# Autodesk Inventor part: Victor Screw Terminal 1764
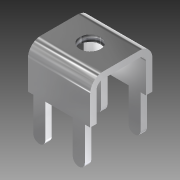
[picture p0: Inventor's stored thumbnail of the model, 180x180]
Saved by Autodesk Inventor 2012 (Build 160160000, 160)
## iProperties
Shininess: 86.0
Length Units: 11272
Angle Units: 11279
Time Units: 11290
Mass Units: 11286
Length Display Precision: 3
Angle Display Precision: 2
Created: 2005-12
Part Number: Victor Screw Terminal 1764
Material: Bronze, Soft Tin
Document SubType Name: Sheet Metal
Designer: t8558es
Density: 1 g/cm^3
Sheet Metal Rule: Default
Density: 0.0
Volumn: 0.0
Area: 0.0
PropertySet Name: Model Information
Control State: 0
Master: False
Checked Out: False
Author: t8558es
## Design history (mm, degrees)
node "Face1"
  sketch "Sketch1"
    geometry: L1 (0, 7.874)-(7.874, 7.874); L2 (7.874, 7.874)-(7.874, 0); L3 (7.874, 0)-(0, 0); L4 (0, 0)-(0, 7.874); 1 further point
    constraints: 8 end point, 2 parallel, 2 point on line, 1 horizontal, 1 perpendicular, 1 other
    dimensions: "d0" = 7.874 distance of L1.start L1.end; "d1" = 7.874 distance of L1.end L2.end
node "Flange1"
node "Flange2"
sketch "Sketch4"
  geometry: L1 (0, -4.623)-(7.874, -4.623) reference; L2 (7.874, -4.623)-(7.874, 0) reference; L3 (7.874, 0)-(0, 0) reference; L4 (0, 0)-(0, -4.623) reference; L5 (3.937, -2.311)-(0, -2.311); L6 (3.937, -2.311)-(7.874, -2.311); L7 (3.937, -2.311)-(3.937, 0); L8 (3.937, -2.311)-(3.937, -4.623)
  constraints: 8 end point, 4 midpoint, 3 collinear, 3 perpendicular
hole "Hole1" sketch "Sketch4" at (3.937, -2.311) diameter "d11" = 2.6416; stored, may be unused: countersink angle "d15" = 82 deg, drill point angle "d17" = 118 deg; dims "d12" = 12.7, "d13" = 9.525, "d14" = 6.35, "d16" = 19.05
node "Flange3"
node "Flange4"
node "Flange5"
node "Flange6"
feature "Corner Round1" dims "d43" = 0.762
body "Solid1"
face "Plate1" dims "Thickness" = 0.8128
sketch "Sketch2"
  geometry: L1 (7.874, 0)-(7.874, -5.334); L2 (7.874, -5.334)-(0, -5.334); 2 other entities
  constraints: 4 end point, 4 other
face "Plate2" dims "d4" = 5.334, "d5" = 90 deg, "d6" = 0.8128 (= BendRadius), "Thickness" = 0.8128, "MinimumRemnant" = 1.6256 (= 2 x Thickness), "BendReliefWidth" = 0.8128 (= Thickness)
bend "Bend1" dims "d3" = 0.8128 (= BendRadius), "d4" = 5.334, "d5" = 90 deg, "d6" = 0.8128 (= BendRadius), "d44" = 0.8128 (= BendReliefWidth), "d45" = 0.4064 (= BendReliefDepth), "d46" = 1.6256 (= MinimumRemnant), "SeamGap" = 0.00508, "Thickness" = 0.8128, "MinimumRemnant" = 1.6256 (= 2 x Thickness), "BendReliefWidth" = 0.8128 (= Thickness)
sketch "Sketch3"
  geometry: L1 (7.874, 0)-(7.874, -5.334); L2 (7.874, -5.334)-(0, -5.334); 2 other entities
  constraints: 4 end point, 4 other
face "Plate3" dims "d8" = 5.334, "d9" = 90 deg, "d10" = 0.8128 (= BendRadius), "Thickness" = 0.8128, "MinimumRemnant" = 1.6256 (= 2 x Thickness), "BendReliefWidth" = 0.8128 (= Thickness)
bend "Bend2" dims "d7" = 0.8128 (= BendRadius), "d8" = 5.334, "d9" = 90 deg, "d10" = 0.8128 (= BendRadius), "d47" = 0.8128 (= BendReliefWidth), "d48" = 0.4064 (= BendReliefDepth), "d49" = 1.6256 (= MinimumRemnant), "SeamGap" = 0.00508, "Thickness" = 0.8128, "MinimumRemnant" = 1.6256 (= 2 x Thickness), "BendReliefWidth" = 0.8128 (= Thickness)
sketch "Sketch5"
  geometry: L1 (0.673, 0)-(2.197, 0); L2 (2.197, 0)-(2.197, 5.004); L3 (2.197, 5.004)-(0.673, 5.004); L4 (0.673, 5.004)-(0.673, 0)
  constraints: 8 end point
face "Plate4" dims "d18" = 0.6731, "d19" = 1.524, "d21" = 5.0038, "d22" = 0, "d23" = 0.8128 (= BendRadius), "Thickness" = 0.8128, "MinimumRemnant" = 1.6256 (= 2 x Thickness), "BendReliefWidth" = 0.8128 (= Thickness)
bend "Bend3" dims "d20" = 0.8128 (= BendRadius), "d21" = 5.0038, "d22" = 0, "d23" = 0.8128 (= BendRadius), "d50" = 0.8128 (= BendReliefWidth), "d51" = 0.4064 (= BendReliefDepth), "d52" = 1.6256 (= MinimumRemnant), "SeamGap" = 0.00508, "Thickness" = 0.8128, "MinimumRemnant" = 1.6256 (= 2 x Thickness), "BendReliefWidth" = 0.8128 (= Thickness)
sketch "Sketch6"
  geometry: L1 (0.673, 0)-(2.197, 0); L2 (2.197, 0)-(2.197, 5.004); L3 (2.197, 5.004)-(0.673, 5.004); L4 (0.673, 5.004)-(0.673, 0)
  constraints: 8 end point
face "Plate5" dims "d25" = 0.6731, "d26" = 1.524, "d28" = 5.0038, "d29" = 0, "d30" = 0.8128 (= BendRadius), "Thickness" = 0.8128, "MinimumRemnant" = 1.6256 (= 2 x Thickness), "BendReliefWidth" = 0.8128 (= Thickness)
bend "Bend4" dims "d27" = 0.8128 (= BendRadius), "d28" = 5.0038, "d29" = 0, "d30" = 0.8128 (= BendRadius), "d53" = 0.8128 (= BendReliefWidth), "d54" = 0.4064 (= BendReliefDepth), "d55" = 1.6256 (= MinimumRemnant), "SeamGap" = 0.00508, "Thickness" = 0.8128, "MinimumRemnant" = 1.6256 (= 2 x Thickness), "BendReliefWidth" = 0.8128 (= Thickness)
sketch "Sketch7"
  geometry: L1 (7.201, 0)-(5.677, 0); L2 (5.677, 0)-(5.677, 5.004); L3 (5.677, 5.004)-(7.201, 5.004); L4 (7.201, 5.004)-(7.201, 0)
  constraints: 8 end point
face "Plate6" dims "d31" = 0.6731, "d32" = 1.524, "d34" = 5.0038, "d35" = 0, "d36" = 0.8128 (= BendRadius), "Thickness" = 0.8128, "MinimumRemnant" = 1.6256 (= 2 x Thickness), "BendReliefWidth" = 0.8128 (= Thickness)
bend "Bend5" dims "d33" = 0.8128 (= BendRadius), "d34" = 5.0038, "d35" = 0, "d36" = 0.8128 (= BendRadius), "d56" = 0.8128 (= BendReliefWidth), "d57" = 0.4064 (= BendReliefDepth), "d58" = 1.6256 (= MinimumRemnant), "SeamGap" = 0.00508, "Thickness" = 0.8128, "MinimumRemnant" = 1.6256 (= 2 x Thickness), "BendReliefWidth" = 0.8128 (= Thickness)
sketch "Sketch8"
  geometry: L1 (0.673, 0)-(2.197, 0); L2 (2.197, 0)-(2.197, 5.004); L3 (2.197, 5.004)-(0.673, 5.004); L4 (0.673, 5.004)-(0.673, 0)
  constraints: 8 end point
face "Plate7" dims "d37" = 0.6731, "d38" = 1.524, "d40" = 5.0038, "d41" = 0, "d42" = 0.8128 (= BendRadius), "Thickness" = 0.8128, "MinimumRemnant" = 1.6256 (= 2 x Thickness), "BendReliefWidth" = 0.8128 (= Thickness)
bend "Bend6" dims "d39" = 0.8128 (= BendRadius), "d40" = 5.0038, "d41" = 0, "d42" = 0.8128 (= BendRadius), "d59" = 0.8128 (= BendReliefWidth), "d60" = 0.4064 (= BendReliefDepth), "d61" = 1.6256 (= MinimumRemnant), "SeamGap" = 0.00508, "Thickness" = 0.8128, "MinimumRemnant" = 1.6256 (= 2 x Thickness), "BendReliefWidth" = 0.8128 (= Thickness)
other parameters: "BendRadius" = 0.8128 (= Thickness), "BendReliefDepth" = 0.4064 (= 0.5 x Thickness), "CornerReliefSize" = 3.2512 (= 4 x Thickness), "TransitionRadius" = 0.8128 (= BendRadius), "d2" = 0.8128 (= BendRadius), "JacobiRadiusSize" = 0.8128 (= Thickness), "GapSize" = 0.8128 (= Thickness)
